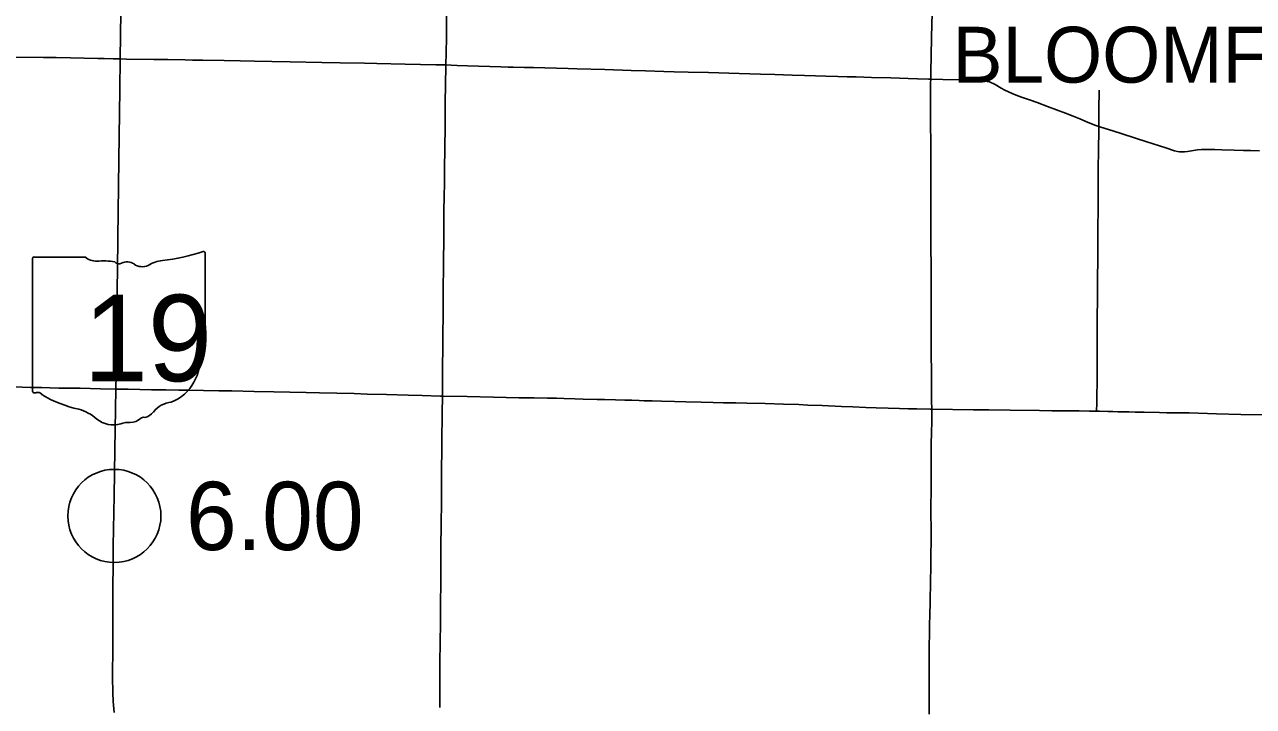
# Model space of a CAD drawing. Extents: x 1813937 to 1948437, y 826606 to 1022856.
# Drawn here: x 1893278 to 1913070, y 961626 to 972609 of the extents above; entities that cross this region are included whole.
import ezdxf

# ---------------------------------------------------------------- set-up
doc = ezdxf.new("R2010")
doc.units = 0
for name, color, linetype in [('Default', 7, 'Continuous'), ('GM_X_County_Road', 7, 'Continuous'), ('GM_X_State_Route', 7, 'Continuous'), ('GM_X_State_Shield', 7, 'Continuous'), ('GM_X_Township_Road', 7, 'Continuous'), ('GM_X_Township_Text', 7, 'Continuous')]:
    doc.layers.add(name, color=color, linetype=linetype)

msp = doc.modelspace()

# ---------------------------------------------------------------- linework, layer by layer
at = {"layer": 'Default'}
msp.add_circle((1894724, 964695), 750, dxfattribs=at)
at = {"layer": 'GM_X_County_Road'}
for points in [[(1907872, 971728), (1907873, 971831), (1907880, 972126), (1907892, 972634), (1907901, 972897), (1907907, 973126), (1907920, 973536), (1907931, 973880), (1907937, 974094), (1907951, 974618), (1907969, 975258), (1907988, 975947), (1907997, 976242), (1908006, 976554), (1908013, 976783), (1908018, 977084)], [(1900063, 971960), (1900066, 972153), (1900071, 972399), (1900076, 972694), (1900080, 972989), (1900087, 973465), (1900091, 973727), (1900097, 974039), (1900100, 974252), (1900102, 974449), (1900108, 974761), (1900109, 974849)], [(1900008, 966625), (1900009, 966823), (1900011, 967168), (1900012, 967331), (1900014, 967495), (1900016, 967626), (1900021, 967921), (1900021, 968036), (1900021, 968233), (1900027, 968823), (1900030, 969119), (1900032, 969332), (1900033, 969578), (1900036, 969873), (1900039, 970021), (1900043, 970283), (1900046, 970611), (1900051, 970972), (1900054, 971316), (1900057, 971677), (1900062, 971907), (1900063, 971960)], [(1907889, 966413), (1907887, 966550), (1907887, 966747), (1907886, 967009), (1907882, 967305), (1907881, 967550), (1907881, 967731), (1907882, 967911), (1907881, 968239), (1907879, 968419), (1907878, 968764), (1907875, 968977), (1907875, 969207), (1907874, 969485), (1907873, 969617), (1907875, 969813), (1907875, 970207), (1907873, 970584), (1907872, 970780), (1907870, 970928), (1907870, 971092), (1907871, 971223), (1907870, 971387), (1907871, 971567), (1907871, 971666), (1907872, 971728)], [(1889520, 966850), (1889815, 966844), (1890339, 966831), (1890552, 966826), (1891142, 966812), (1891355, 966807), (1891551, 966803), (1891715, 966799), (1891830, 966797), (1891928, 966795), (1892240, 966789), (1892486, 966783), (1892912, 966776), (1893027, 966774), (1893240, 966769), (1893371, 966766), (1893551, 966761), (1893830, 966755), (1893978, 966753), (1894174, 966750), (1894502, 966742), (1894748, 966737)], [(1894748, 966737), (1894945, 966734), (1895322, 966728), (1895552, 966724), (1895765, 966721), (1895912, 966718), (1896404, 966712), (1896618, 966708), (1896978, 966701), (1897290, 966695), (1897552, 966689), (1897814, 966684), (1898027, 966678), (1898585, 966665), (1898798, 966658), (1899109, 966650), (1899454, 966641), (1899683, 966634), (1899978, 966626), (1900008, 966625)], [(1899967, 961609), (1899965, 961822), (1899965, 961937), (1899965, 962297), (1899966, 962363), (1899967, 962445), (1899970, 962542), (1899970, 962689), (1899975, 962935), (1899977, 963181), (1899979, 963377), (1899980, 963525), (1899982, 963918), (1899984, 964213), (1899986, 964541), (1899986, 964606), (1899991, 964874), (1899992, 964955), (1899994, 965332), (1899999, 965873), (1900001, 966037), (1900002, 966200), (1900006, 966430), (1900007, 966545), (1900008, 966625)], [(1900008, 966625), (1900404, 966617), (1900830, 966608), (1901240, 966599), (1901404, 966596), (1901486, 966595), (1901699, 966591), (1901847, 966589), (1901961, 966585), (1902142, 966580), (1902273, 966575), (1902502, 966571), (1902617, 966568), (1902797, 966563), (1902945, 966559), (1903059, 966557), (1903174, 966554), (1903256, 966551), (1903387, 966546), (1903534, 966543), (1903748, 966539), (1903928, 966534), (1904174, 966528), (1904371, 966522), (1904534, 966519), (1904649, 966517), (1904731, 966517), (1904911, 966511), (1905206, 966503), (1905501, 966496), (1905747, 966487), (1905895, 966481), (1906124, 966472), (1906435, 966459), (1906616, 966452), (1906829, 966442), (1906993, 966437), (1907189, 966431), (1907369, 966425), (1907517, 966421), (1907648, 966418), (1907862, 966413), (1907889, 966413)], [(1907846, 961503), (1907846, 961831), (1907847, 962045), (1907847, 962143), (1907847, 962274), (1907846, 962339), (1907846, 962454), (1907849, 962634), (1907852, 962765), (1907855, 962929), (1907859, 963110), (1907862, 963290), (1907866, 963437), (1907867, 963519), (1907869, 963601), (1907871, 963700), (1907873, 963814), (1907873, 963896), (1907873, 963961), (1907874, 964060), (1907878, 964305), (1907878, 964436), (1907876, 964781), (1907877, 964928), (1907878, 965026), (1907878, 965157), (1907879, 965256), (1907879, 965387), (1907880, 965633), (1907882, 965813), (1907887, 966075), (1907888, 966174), (1907889, 966305), (1907889, 966370), (1907889, 966413)], [(1907889, 966413), (1908561, 966405), (1908807, 966401), (1909152, 966398), (1909627, 966392), (1909824, 966390), (1910004, 966390), (1910134, 966389), (1910264, 966386), (1910428, 966382), (1910544, 966382)], [(1910544, 966382), (1910592, 966381), (1910723, 966378), (1910805, 966376), (1910887, 966374), (1911067, 966371), (1911165, 966368), (1911313, 966365), (1911559, 966359), (1911673, 966356), (1911788, 966355), (1912034, 966353), (1912474, 966339), (1912869, 966331), (1913655, 966320)]]:
    msp.add_lwpolyline(points, dxfattribs=at)
at = {"layer": 'GM_X_State_Route'}
msp.add_lwpolyline([(1894720, 961531), (1894706, 961705), (1894698, 961852), (1894696, 962098), (1894698, 962590), (1894700, 963132), (1894700, 963493), (1894702, 963952), (1894705, 964215), (1894719, 965019), (1894733, 965757), (1894743, 966413), (1894748, 966737), (1894757, 967201), (1894760, 967529), (1894766, 968021), (1894770, 968366), (1894775, 968661), (1894782, 969170), (1894796, 970433), (1894811, 971565), (1894818, 972056), (1894829, 972812)], dxfattribs=at)
at = {"layer": 'GM_X_State_Shield'}
for p, q in [((1894246, 968865), (1893431, 968865)), ((1896188, 967812), (1896188, 968918)), ((1893403, 968829), (1893403, 966716)), ((1896187, 967813), (1896188, 967812))]:
    msp.add_line(p, q, dxfattribs=at)
for centre, radius, start, end in [((1893435, 968834), 32.3, 98.1301, 188.1301), ((1894440, 969111), 313, 231.6195, 271.1119), ((1895196, 971747), 2953, 275.8445, 288.9065), ((1896157, 968922), 31, 351.8621, 97.738), ((1894544, 967679), 1123, 80.4867, 94.9883), ((1894799, 968845), 90.3, 219.7921, 297.1024), ((1894932, 968600), 188, 54.4667, 119.1411), ((1895174, 968935), 226, 233.8562, 294.8282), ((1895573, 968220), 594, 97.3462, 120.7689), ((1896181, 967731), 48, 107.944, 210.337), ((1895875, 967591), 288, 340.033, 23.6496), ((1896155, 967808), 33.2, 289.6038, 7.7341), ((1896299, 967350), 210, 136.8065, 186.9296), ((1895361, 967209), 739, 292.3089, 8.9858), ((1893436, 966711), 32.5, 171.9584, 258.3066), ((1893441, 966927), 248, 267.339, 280.6039), ((1893491, 966594), 89.5, 29.7484, 93.2717), ((1894622, 968493), 2132, 240.4129, 257.1985), ((1895673, 966123), 404, 94.4031, 142.5768), ((1893986, 965766), 667, 47.1842, 75.836), ((1894983, 966425), 226, 268.777, 315.5493), ((1895187, 966220), 63.5, 65.7517, 132.6484), ((1895160, 966511), 239, 282.8732, 323.2771), ((1894708, 966583), 423, 230.7004, 286.2918), ((1894952, 965853), 348, 85.6951, 111.2099)]:
    msp.add_arc(centre, radius, start, end, dxfattribs=at)
at = {"layer": 'GM_X_Township_Road'}
for points in [[(1889618, 972143), (1889654, 972142), (1890163, 972136), (1890491, 972130), (1890917, 972121), (1891278, 972116), (1891623, 972111), (1891902, 972107), (1892591, 972095), (1893132, 972086), (1893584, 972080), (1893789, 972077), (1894018, 972071), (1894460, 972064), (1894558, 972062), (1894706, 972059), (1894818, 972056)], [(1894818, 972056), (1894917, 972053), (1895362, 972046), (1895587, 972044), (1895864, 972040), (1895985, 972038), (1896150, 972036), (1896492, 972029), (1896752, 972024), (1896981, 972021), (1897260, 972017), (1897556, 972011), (1898064, 972000), (1898359, 971995), (1898753, 971987), (1898950, 971983), (1899409, 971974), (1899655, 971968), (1899902, 971963), (1900049, 971960), (1900063, 971960)], [(1900063, 971960), (1900147, 971956), (1900246, 971952), (1900410, 971947), (1900951, 971929), (1901065, 971925), (1901147, 971923), (1901328, 971920), (1901475, 971916), (1901656, 971911), (1902033, 971902), (1902180, 971897), (1902623, 971883), (1903049, 971870), (1903279, 971864), (1903574, 971855), (1903738, 971850), (1903968, 971843), (1904296, 971835), (1904788, 971822), (1905132, 971811), (1905362, 971804), (1905641, 971795), (1905837, 971787), (1906018, 971784), (1906182, 971780), (1906379, 971774), (1906526, 971770), (1906674, 971765), (1906920, 971759), (1907232, 971749), (1907510, 971740), (1907658, 971735), (1907838, 971729), (1907872, 971728)], [(1907872, 971728), (1908068, 971724), (1908412, 971718), (1908609, 971714), (1908675, 971711), (1908724, 971707), (1908756, 971702), (1908788, 971694), (1908819, 971685), (1908850, 971673), (1908880, 971659), (1908909, 971644), (1909007, 971584), (1909065, 971553), (1909124, 971525), (1909184, 971500), (1909276, 971464), (1909353, 971436), (1909477, 971393), (1909585, 971354), (1909754, 971290), (1910045, 971180), (1910168, 971132), (1910274, 971089), (1910411, 971033), (1910533, 970985), (1910579, 970968)], [(1910579, 970968), (1910579, 970976), (1910579, 971018), (1910580, 971083), (1910580, 971132), (1910581, 971206), (1910582, 971353), (1910583, 971435), (1910583, 971551)], [(1910544, 966382), (1910545, 966404), (1910546, 966490), (1910550, 966671), (1910551, 966811), (1910552, 966910), (1910553, 967177), (1910555, 967555), (1910555, 967702), (1910555, 967949), (1910557, 968129), (1910560, 968425), (1910561, 968606), (1910562, 968739), (1910562, 968815), (1910563, 968910), (1910563, 968995), (1910563, 969061), (1910564, 969121), (1910564, 969186), (1910565, 969256), (1910566, 969453), (1910567, 969519), (1910568, 969552), (1910570, 969633), (1910571, 969696), (1910572, 969748), (1910572, 969797), (1910572, 969961), (1910571, 970043), (1910572, 970191), (1910577, 970684), (1910578, 970815), (1910579, 970926), (1910579, 970968)], [(1910579, 970968), (1910610, 970956), (1910735, 970917), (1910923, 970858), (1911204, 970768), (1911455, 970689), (1911658, 970624), (1911798, 970578), (1911846, 970566), (1911878, 970560), (1911910, 970557), (1911960, 970559), (1912009, 970564), (1912106, 970580), (1912171, 970589), (1912236, 970595), (1912302, 970597), (1912449, 970596), (1912564, 970593), (1912761, 970588), (1912908, 970583), (1913023, 970580), (1913170, 970573)]]:
    msp.add_lwpolyline(points, dxfattribs=at)

# ---------------------------------------------------------------- texts
at = {"layer": 'Default'}
msp.add_text('6.00', height=1100, dxfattribs=at).set_placement((1895877, 964145))
at = {"layer": 'GM_X_State_Shield'}
msp.add_text('19', height=1392.2, dxfattribs=at).set_placement((1894228, 966865))
at = {"layer": 'GM_X_Township_Text'}
msp.add_text('BLOOMFIELD', height=900, rotation=0, dxfattribs=at).set_placement((1908226, 971674))

doc.saveas('drawing.dxf')
